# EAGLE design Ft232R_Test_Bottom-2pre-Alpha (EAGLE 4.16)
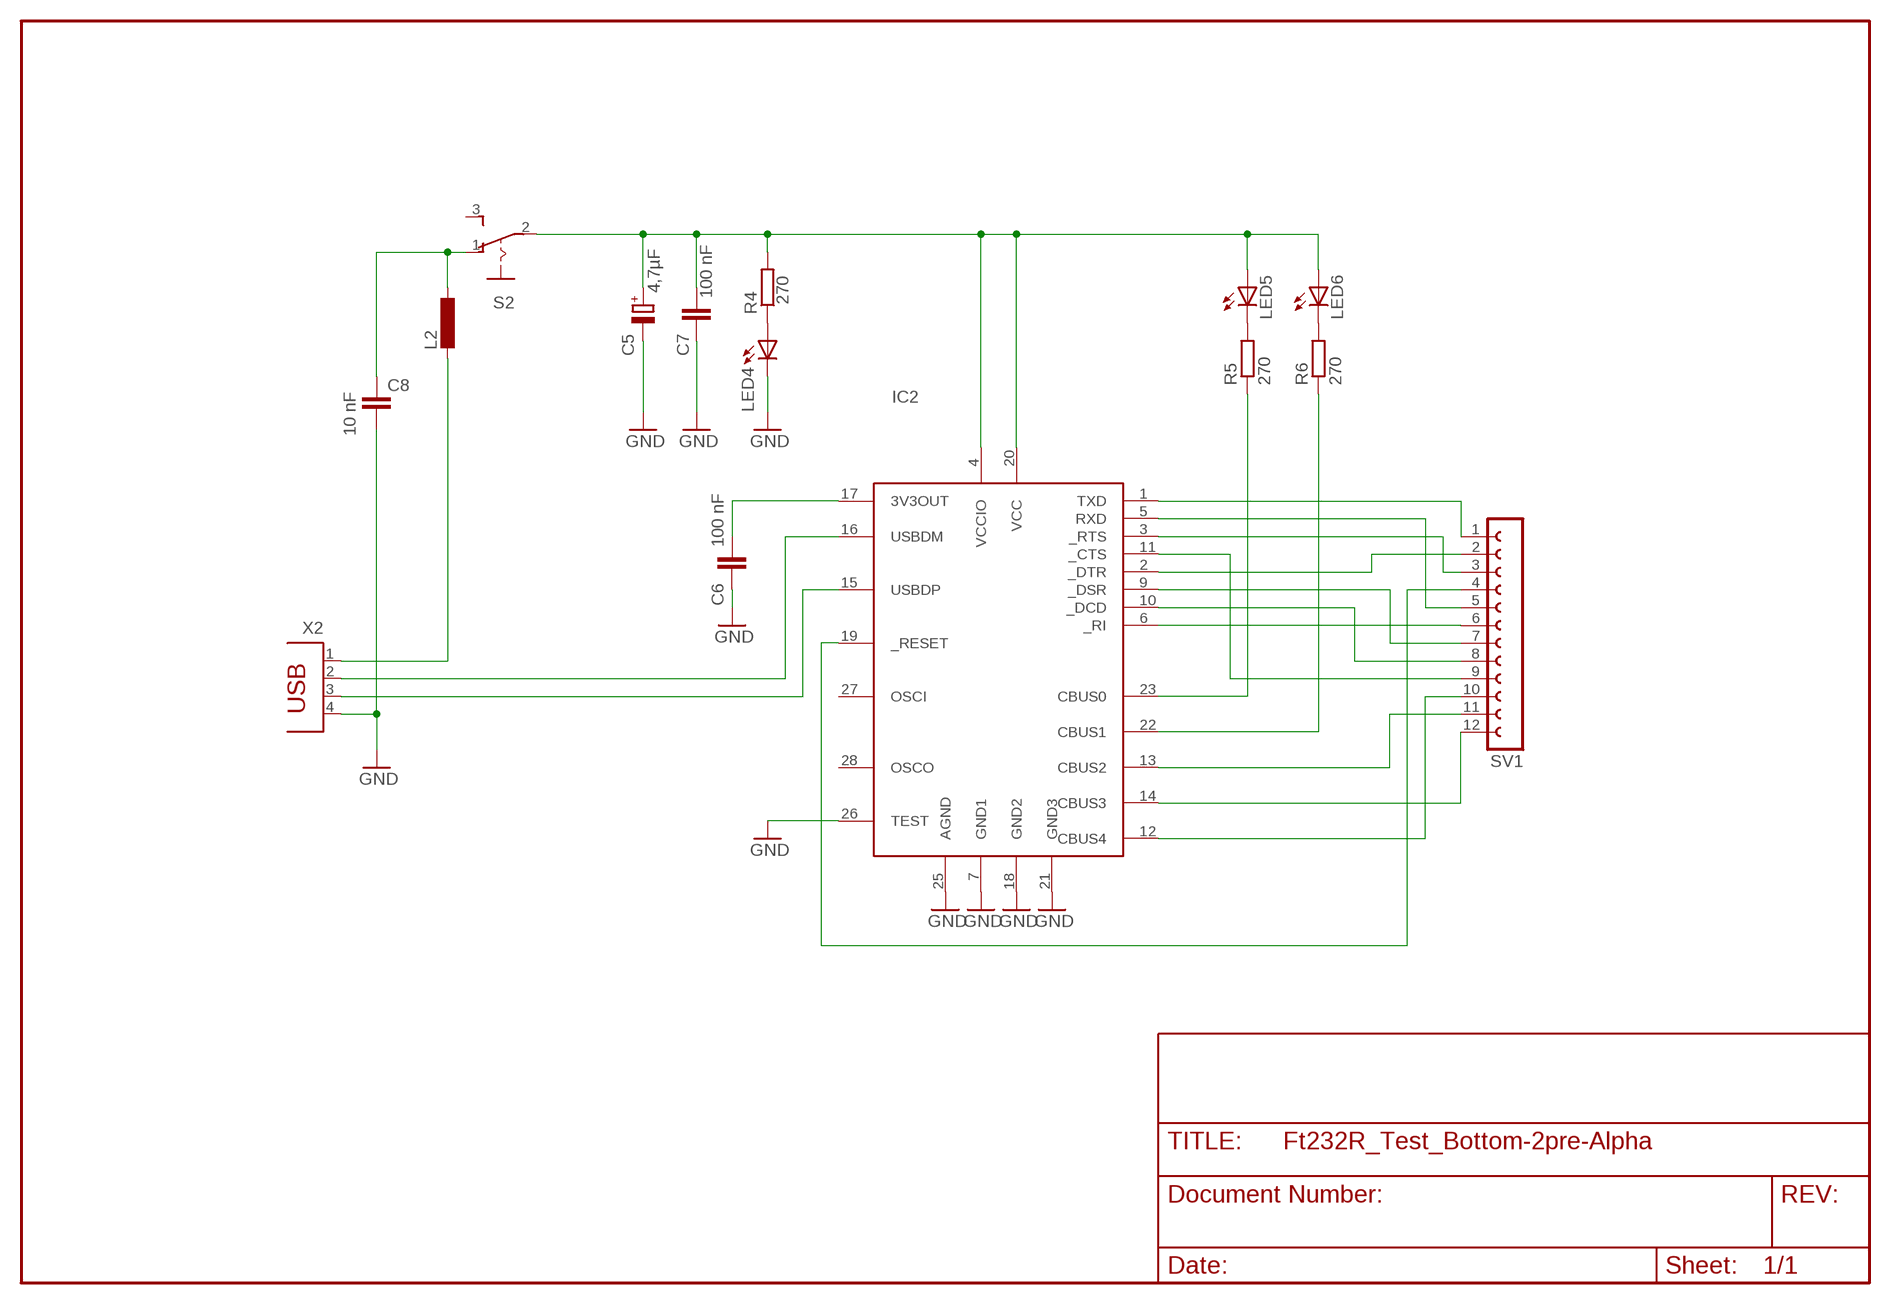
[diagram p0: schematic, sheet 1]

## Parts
C5  4,7µF  CPOL-EUE5-6  [E5-6]
C6  100 nF  C-EU050-024X044  [C050-024X044]
C7  100 nF  C-EU050-024X044  [C050-024X044]
C8  10 nF  C-EU050-024X044  [C050-024X044]
IC2  FT232RL  [SSOP28DB]
L2  L-EU0207/7  [0207/7]
LED4  LED5MM  [LED5MM]
LED5  LED5MM  [LED5MM]
LED6  LED5MM  [LED5MM]
R4  270  R-EU_0207/7  [0207/7]
R5  270  R-EU_0207/7  [0207/7]
R6  270  R-EU_0207/7  [0207/7]
S2  255SB  [255SB]
SV1  FE12-1  [FE12]
X2  PN61729  [PN61729]

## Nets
GND: C5.- C6.2 C7.2 C8.2 IC2.7(GND1) IC2.18(GND2) IC2.21(GND3) IC2.25(AGND) IC2.26(TEST) LED4.K(C) X2.4
N$1: C8.1 L2.1 S2.1(O)
N$2: L2.2 X2.1
N$3: LED4.A R4.1
N$4: LED5.K(C) R5.2
N$5: LED6.K(C) R6.2
N$6: IC2.1(TXD) SV1.1
N$7: IC2.2(_DTR) SV1.2
N$8: IC2.3(_RTS) SV1.3
N$9: IC2.5(RXD) SV1.5
N$10: IC2.6(_RI) SV1.6
N$11: IC2.9(_DSR) SV1.7
N$12: IC2.10(_DCD) SV1.8
N$13: IC2.11(_CTS) SV1.9
N$14: IC2.19(_RESET) SV1.4
N$15: IC2.13(CBUS2) SV1.11
N$16: IC2.14(CBUS3) SV1.12
N$17: IC2.12(CBUS4) SV1.10
N$18: C6.1 IC2.17(3V3OUT)
RX-LED1: IC2.22(CBUS1) R6.1
TX-LED1: IC2.23(CBUS0) R5.1
USBDM1: IC2.16(USBDM) X2.2
USBDP1: IC2.15(USBDP) X2.3
VCC1: C5.+ C7.1 IC2.4(VCCIO) IC2.20(VCC) LED5.A LED6.A R4.2 S2.2(P)
Unconnected: IC2.27(OSCI) IC2.28(OSCO) S2.3(S)

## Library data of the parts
C5 = rcl:CPOL-EU: POLARIZED CAPACITOR, European symbol
C6-C8 = rcl:C-EU: CAPACITOR, European symbol
IC2 = ftdichip-1:FT232RL: USB UART 4th Generation USB UART (USB <-> Serial) Controller
L2 = rcl:L-EU: INDUCTOR, European symbol
LED4-LED6 = led:LED: LED
R4-R6 = rcl:R-EU_: RESISTOR, European symbol
S2 = switch:255SB: SLIDING SWITCH distributor Buerklin, 11G810
SV1 = con-lsta:FE12-1: FEMALE HEADER
X2 = con-berg:PN61729: BERG USB connector

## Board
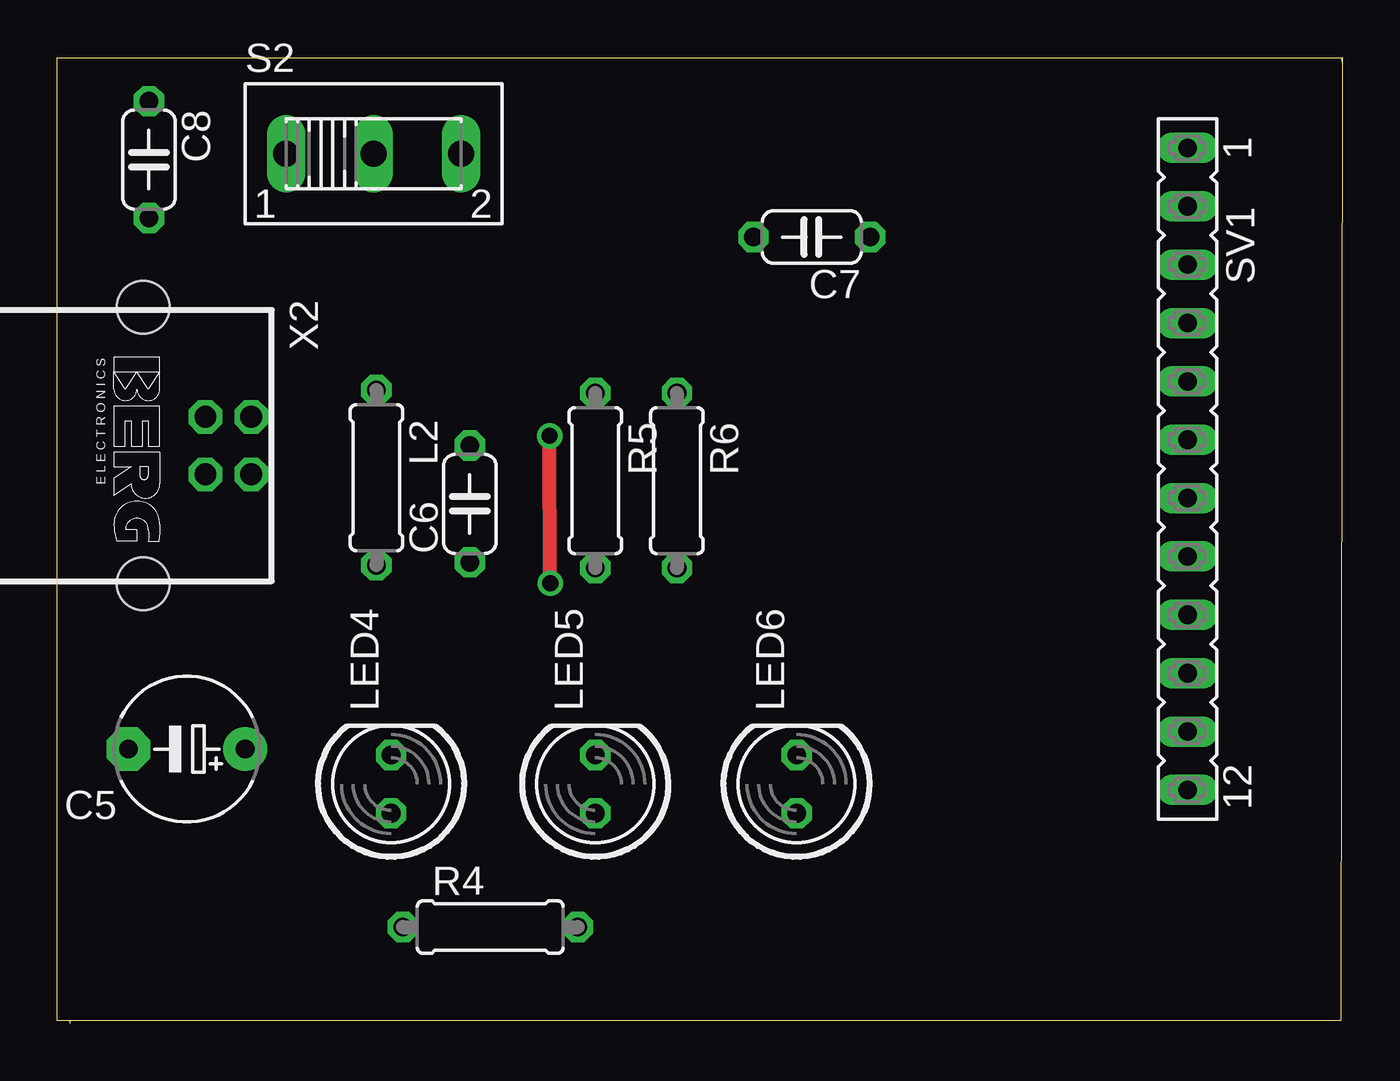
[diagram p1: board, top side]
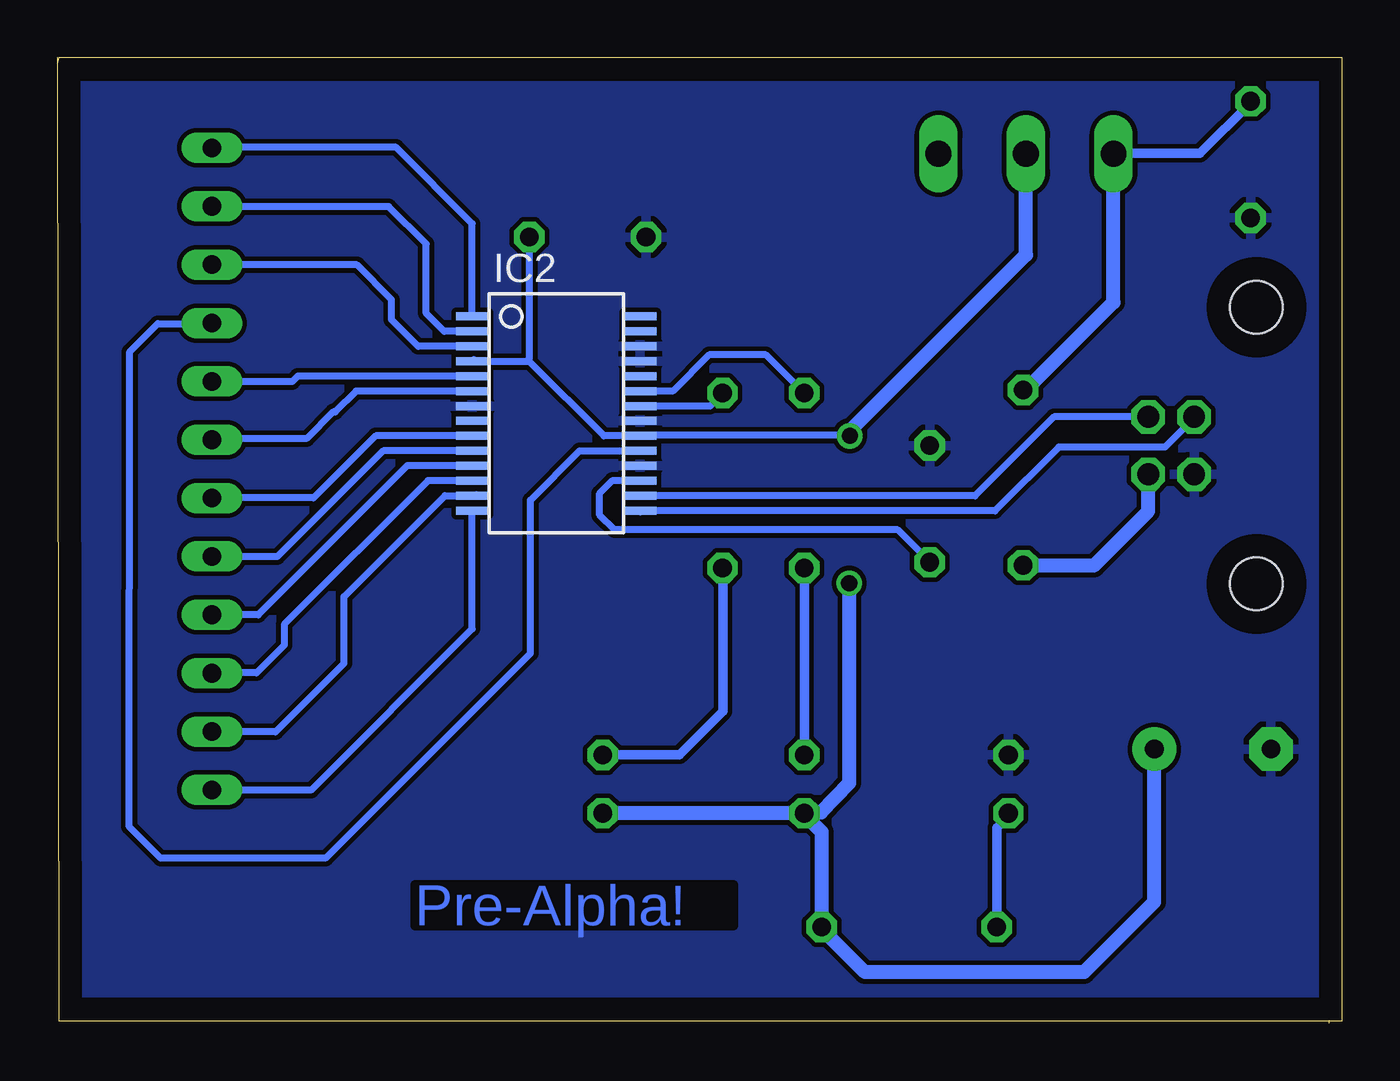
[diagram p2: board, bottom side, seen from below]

Size 55.93 x 42.04 mm. Coordinates in mm from the lower left corner, seen from the top.
Outline: 55.93,42.04 55.93,41.78
Outline: 55.93,41.78 55.88,0.11 0,0.11 0,42.02 55.88,42.02 55.93,41.78
Outline: 0.56,0 0.56,0.13
Copper layers (1*16): Top 0.035mm / dielectric 1.5mm / Bottom 0.035mm
Design rules "default": minimum track width 10mil, minimum drill 24mil, track to track 8mil, track to pad 8mil, pad to pad 8mil, via to via 8mil, smd to smd 8mil, copper to edge 40mil, drill to drill 8mil, minimum pad ring 10mil, minimum via ring 8mil, stop-mask expansion 4mil, vias tented up to drill 0mil, thermal gap 10mil

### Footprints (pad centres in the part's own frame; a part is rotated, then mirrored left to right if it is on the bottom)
E5-6 = drill 0.813 pad 1.905 round: + -2.54,0 | drill 0.813 pad 1.905 octagon: - 2.54,0
C050-024X044 = drill 0.813 octagon: 1 -2.54,0; 2 2.54,0
SSOP28DB = smd 0.348 x 1.397: 1 -4.225,-3.656; 2 -3.575,-3.656; 3 -2.925,-3.656; 4 -2.275,-3.656; 5 -1.625,-3.656; 6 -0.975,-3.656; 7 -0.325,-3.656; 8 0.325,-3.656; 9 0.975,-3.656; 10 1.625,-3.656; 11 2.275,-3.656; 12 2.925,-3.656; 13 3.575,-3.656; 14 4.225,-3.656; 15 4.225,3.656; 16 3.575,3.656; 17 2.925,3.656; 18 2.275,3.656; 19 1.625,3.656; 20 0.975,3.656; 21 0.325,3.656; 22 -0.325,3.656; 23 -0.975,3.656; 24 -1.625,3.656; 25 -2.275,3.656; 26 -2.925,3.656; 27 -3.575,3.656; 28 -4.225,3.656
0207/7 = drill 0.813 octagon: 1 -3.81,0; 2 3.81,0
LED5MM = drill 0.813 octagon: A -1.27,0; K 1.27,0
255SB = drill 1.118 long: 1 -3.81,0; 2 0,0; 3 3.81,0
FE12 = drill 0.813 long: 1 -13.97,0; 2 -11.43,0; 3 -8.89,0; 4 -6.35,0; 5 -3.81,0; 6 -1.27,0; 7 1.27,0; 8 3.81,0; 9 6.35,0; 10 8.89,0; 11 11.43,0; 12 13.97,0
PN61729 = drill 0.95 octagon: 1 1.25,4.71; 2 -1.25,4.71; 3 -1.25,2.71; 4 1.25,2.71 | hole 2.3: -6.02,0; 6.02,0

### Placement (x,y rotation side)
C5  5.63,11.94 180 top
C6  17.95,22.61 90 top
C7  32.84,34.22 180 top
C8  3.98,37.59 270 top
IC2  34.21,26.54 270 bottom
L2  13.89,23.75 270 top
LED4  14.53,10.41 90 top
LED5  23.41,10.41 90 top
LED6  32.18,10.41 90 top
R4  18.84,4.19 0 top
R5  23.41,23.62 270 top
R6  26.97,23.62 270 top
S2  13.76,37.85 0 top
SV1  49.2,24.13 270 top
X2  3.73,25.15 270 top

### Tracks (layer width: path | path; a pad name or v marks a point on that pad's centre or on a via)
GND
  pour Bottom: 0,42.02 55.8,41.66 55.88,0.11 0,0.11
N$1
  Bottom 0.406: C8.1 3.98,40.07 6.19,37.86 9.72,37.86 9.83,37.75 9.93,37.85 S2.1 | 13.91,27.42 13.89,27.44 L2.1
  Bottom 0.61: S2.1 9.95,31.38 13.89,27.44
N$2
  Bottom 0.406: 13.97,19.92 13.94,19.94 L2.2
  Bottom 0.61: X2.1 8.44,22.29 10.81,19.92 13.97,19.92
N$3
  Bottom 0.406: LED4.A 14.53,9.07 14.5,9.04 15.03,8.51 R4.1
N$4
  Bottom 0.406: 23.49,19.81 23.51,19.83 | 23.49,19.81 R5.2 | LED5.K 23.41,19.73 23.49,19.81
N$5
  Bottom 0.406: LED6.K 28.84,11.68 26.95,13.57 26.95,19.78 R6.2 | R6.2 27,19.83 | R6.2
N$6
  Bottom 0.305: IC2.1 37.87,34.8 41.18,38.12 49.22,38.12 | 49.22,38.12 SV1.1 | 49.22,38.12 49.26,38.16
N$7
  Bottom 0.305: IC2.2 39.09,30.12 39.88,30.9 39.88,33.92 41.5,35.54 49.1,35.54 49.14,35.58 49.16,35.56 SV1.2
N$8
  Bottom 0.305: IC2.3 40.22,29.47 41.38,30.63 41.38,31.5 42.88,33 49.22,33 49.23,33.02 | 49.23,33.02 49.26,33.04 | 49.23,33.02 SV1.3
N$9
  Bottom 0.305: IC2.5 45.47,28.17 45.7,27.93 49.22,27.93 49.23,27.94 | 49.23,27.94 49.3,28.01 | 49.23,27.94 SV1.5
N$10
  Bottom 0.305: 49.26,25.39 49.26,25.4 SV1.6 49.16,25.4 49.11,25.44 45.09,25.44 43.91,26.62 43.83,26.62 42.93,27.52 IC2.6
N$11
  Bottom 0.305: IC2.9 42.07,25.57 44.77,22.87 49.21,22.87 SV1.7
N$12
  Bottom 0.305: IC2.10 41.75,24.92 46.36,20.31 49.19,20.31 SV1.8
N$13
  Bottom 0.305: IC2.11 40.7,24.27 47.19,17.78 49.11,17.78 | 49.11,17.78 | 49.11,17.78 SV1.9
N$14
  Bottom 0.305: IC2.19 33.2,24.92 35.34,22.78 35.34,16.11 44.25,7.19 51.44,7.19 52.79,8.55 52.77,29.24 51.55,30.46 49.05,30.46 49.07,30.48 SV1.4
N$15
  Bottom 0.305: 37.69,23.01 37.73,22.97 IC2.13 39.05,22.97 43.45,18.57 43.45,15.66 46.43,12.68 49.26,12.68 49.24,12.7 SV1.11
N$16
  Bottom 0.305: IC2.14 37.87,17.17 44.88,10.15 49.07,10.15 49.08,10.16 SV1.12
N$17
  Bottom 0.305: IC2.12 39.8,23.62 46.05,17.36 46.05,16.46 47.26,15.25 49.22,15.25 | 49.22,15.25 49.22,15.24 SV1.10 | 49.22,15.25 49.26,15.29
N$18
  Bottom 0.305: C6.1 17.95,20.09 19.34,21.48 31.68,21.48 32.32,22.12 32.32,23.07 31.75,23.63 30.51,23.63 30.52,23.62 IC2.17
RX-LED1
  Bottom 0.305: 26.95,27.43 26.9,27.47 | R6.1 26.95,27.43 | IC2.22 27.51,26.87 26.95,27.43
TX-LED1
  Bottom 0.305: IC2.23 29.13,27.52 27.56,29.09 25.09,29.09 23.41,27.41 | 23.41,27.41 23.39,27.39 | R5.1 23.41,27.41
USBDM1
  Bottom 0.305: X2.2 12.54,26.4 15.98,22.96 30.49,22.96 30.5,22.97 IC2.16
USBDP1
  Bottom 0.305: X2.3 6.44,26.36 7.71,25.08 12.33,25.08 15.11,22.31 30.49,22.31 30.55,22.25 30.55,22.26 IC2.15
VCC1  (via drill 0.7)
  Top 0.61: v21.46,19.16 v21.43,25.57
  Bottom 0.305: 21.66,25.58 30.62,25.58 30.6,25.57 IC2.20 32.14,25.57 35.37,28.8 35.44,28.8 | 35.44,28.8 37.73,28.8 37.77,28.85 37.8,28.82 IC2.4 37.85,28.82 | 37.85,28.82 37.79,28.88 | 37.85,28.82 IC2.4 | 35.44,28.8 35.44,28.88 35.38,28.94 C7.1 | 22.66,4.12 22.65,4.13 R4.2 | 32.34,9.18 22.68,9.18 | 21.57,25.58 21.56,25.58 21.59,25.61 | v21.43,25.57 21.48,25.63
  Bottom 0.406: 23.51,9.18 23.48,9.14 LED5.A | LED6.A 32.31,9.14 32.34,9.18 | 21.59,25.61 21.66,25.58 | 21.48,25.63 21.56,25.58
  Bottom 0.61: R4.2 22.65,8.32 23.48,9.14 | LED5.A 32.31,9.14 | S2.2 13.76,33.44 21.59,25.61 | C5.+ 8.18,5.29 11.24,2.23 20.76,2.23 22.66,4.12 | 22.68,9.18 21.46,10.46 v21.46,19.16

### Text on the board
Bottom: Pre-Alpha!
